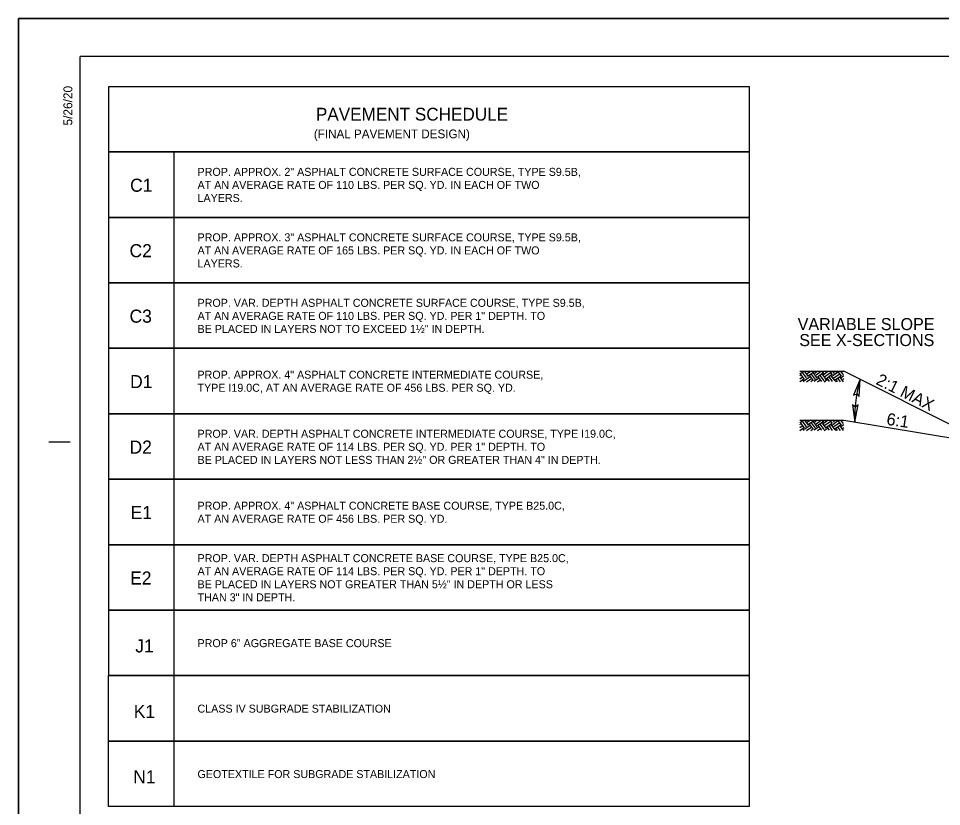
# Model space of a CAD drawing. Extents: x 1184121 to 1184397, y 1246506 to 1246661.
# Drawn here: x 1184121.1 to 1184197.8, y 1246595 to 1246660.5 of the extents above; entities that cross this region are included whole.
import ezdxf

# ---------------------------------------------------------------- set-up
doc = ezdxf.new("R2010")
doc.units = 0
for name, color, linetype in [('Sheet Data Field CELL', 7, 'Continuous'), ('Sheet Plan CELL', 7, 'Continuous'), ('Sheet Plot Border Outside CELL', 7, 'Continuous'), ('z - Construction', 7, 'Continuous')]:
    doc.layers.add(name, color=color, linetype=linetype)

msp = doc.modelspace()

# ---------------------------------------------------------------- linework, layer by layer
at = {"layer": 'Sheet Data Field CELL'}
for p, q in [((1184185.976, 1246631.202), (1184189.63, 1246631.202)), ((1184185.976, 1246631.202), (1184189.63, 1246631.202)), ((1184185.99, 1246630.99), (1184186.286, 1246631.202)), ((1184185.99, 1246630.99), (1184186.286, 1246631.202)), ((1184186.53, 1246630.645), (1184186.221, 1246631.075)), ((1184186.53, 1246630.645), (1184186.221, 1246631.075)), ((1184186.691, 1246630.761), (1184186.382, 1246631.19)), ((1184186.691, 1246630.761), (1184186.382, 1246631.19)), ((1184186.474, 1246631.175), (1184186.513, 1246631.203)), ((1184186.474, 1246631.175), (1184186.513, 1246631.203)), ((1184186.59, 1246631.014), (1184186.855, 1246631.204)), ((1184186.59, 1246631.014), (1184186.855, 1246631.204)), ((1184186.706, 1246630.853), (1184187.136, 1246631.162)), ((1184186.706, 1246630.853), (1184187.136, 1246631.162)), ((1184187.429, 1246630.64), (1184187.121, 1246631.069)), ((1184187.429, 1246630.64), (1184187.121, 1246631.069)), ((1184187.228, 1246631.147), (1184187.186, 1246631.205)), ((1184187.228, 1246631.147), (1184187.186, 1246631.205)), ((1184187.213, 1246631.054), (1184187.424, 1246631.206)), ((1184187.213, 1246631.054), (1184187.424, 1246631.206)), ((1184187.329, 1246630.893), (1184187.758, 1246631.202)), ((1184187.329, 1246630.893), (1184187.758, 1246631.202)), ((1184187.966, 1246631.026), (1184187.836, 1246631.207)), ((1184187.966, 1246631.026), (1184187.836, 1246631.207)), ((1184187.951, 1246630.933), (1184188.334, 1246631.208)), ((1184187.951, 1246630.933), (1184188.334, 1246631.208)), ((1184188.067, 1246630.772), (1184188.497, 1246631.081)), ((1184188.067, 1246630.772), (1184188.497, 1246631.081)), ((1184188.128, 1246631.141), (1184188.08, 1246631.208)), ((1184188.128, 1246631.141), (1184188.08, 1246631.208)), ((1184188.705, 1246630.905), (1184188.491, 1246631.202)), ((1184188.705, 1246630.905), (1184188.491, 1246631.202)), ((1184188.69, 1246630.813), (1184189.119, 1246631.121)), ((1184188.69, 1246630.813), (1184189.119, 1246631.121)), ((1184188.866, 1246631.021), (1184188.73, 1246631.209)), ((1184188.866, 1246631.021), (1184188.73, 1246631.209)), ((1184189.027, 1246631.136), (1184188.98, 1246631.202)), ((1184189.027, 1246631.136), (1184188.98, 1246631.202)), ((1184189.443, 1246630.784), (1184189.143, 1246631.202)), ((1184189.443, 1246630.784), (1184189.143, 1246631.202)), ((1184189.604, 1246630.9), (1184189.387, 1246631.202)), ((1184189.604, 1246630.9), (1184189.387, 1246631.202)), ((1184201.788, 1246625.123), (1184189.63, 1246631.202)), ((1184185.99, 1246630.827), (1184186.045, 1246630.866)), ((1184185.99, 1246630.827), (1184186.045, 1246630.866)), ((1184185.99, 1246630.583), (1184186.161, 1246630.705)), ((1184185.99, 1246630.583), (1184186.161, 1246630.705)), ((1184185.99, 1246630.338), (1184186.276, 1246630.544)), ((1184185.99, 1246630.338), (1184186.276, 1246630.544)), ((1184186.369, 1246630.529), (1184186.06, 1246630.959)), ((1184186.369, 1246630.529), (1184186.06, 1246630.959)), ((1184186.351, 1246630.327), (1184186.261, 1246630.452)), ((1184186.351, 1246630.327), (1184186.261, 1246630.452)), ((1184186.354, 1246630.437), (1184186.783, 1246630.746)), ((1184186.354, 1246630.437), (1184186.783, 1246630.746)), ((1184186.541, 1246630.327), (1184186.899, 1246630.584)), ((1184186.541, 1246630.327), (1184186.899, 1246630.584)), ((1184187.107, 1246630.408), (1184186.798, 1246630.838)), ((1184187.107, 1246630.408), (1184186.798, 1246630.838)), ((1184186.881, 1246630.327), (1184187.015, 1246630.423)), ((1184186.881, 1246630.327), (1184187.015, 1246630.423)), ((1184187.268, 1246630.524), (1184186.959, 1246630.954)), ((1184187.268, 1246630.524), (1184186.959, 1246630.954)), ((1184187.169, 1246630.371), (1184187.522, 1246630.625)), ((1184187.169, 1246630.371), (1184187.522, 1246630.625)), ((1184187.444, 1246630.732), (1184187.874, 1246631.041)), ((1184187.444, 1246630.732), (1184187.874, 1246631.041)), ((1184187.448, 1246630.327), (1184187.637, 1246630.464)), ((1184187.448, 1246630.327), (1184187.637, 1246630.464)), ((1184187.794, 1246630.359), (1184187.537, 1246630.717)), ((1184187.794, 1246630.359), (1184187.537, 1246630.717)), ((1184188.007, 1246630.403), (1184187.698, 1246630.833)), ((1184188.007, 1246630.403), (1184187.698, 1246630.833)), ((1184188.168, 1246630.519), (1184187.859, 1246630.949)), ((1184188.168, 1246630.519), (1184187.859, 1246630.949)), ((1184188.015, 1246630.327), (1184188.26, 1246630.504)), ((1184188.015, 1246630.327), (1184188.26, 1246630.504)), ((1184188.183, 1246630.611), (1184188.613, 1246630.92)), ((1184188.183, 1246630.611), (1184188.613, 1246630.92)), ((1184188.455, 1246630.345), (1184188.275, 1246630.596)), ((1184188.455, 1246630.345), (1184188.275, 1246630.596)), ((1184188.703, 1246630.34), (1184188.436, 1246630.712)), ((1184188.703, 1246630.34), (1184188.436, 1246630.712)), ((1184188.906, 1246630.398), (1184188.597, 1246630.828)), ((1184188.906, 1246630.398), (1184188.597, 1246630.828)), ((1184188.806, 1246630.651), (1184189.235, 1246630.96)), ((1184188.806, 1246630.651), (1184189.235, 1246630.96)), ((1184188.921, 1246630.49), (1184189.351, 1246630.799)), ((1184188.921, 1246630.49), (1184189.351, 1246630.799)), ((1184188.933, 1246630.336), (1184188.998, 1246630.383)), ((1184188.933, 1246630.336), (1184188.998, 1246630.383)), ((1184189.116, 1246630.332), (1184189.014, 1246630.475)), ((1184189.116, 1246630.332), (1184189.014, 1246630.475)), ((1184189.364, 1246630.327), (1184189.175, 1246630.591)), ((1184189.364, 1246630.327), (1184189.175, 1246630.591)), ((1184189.612, 1246630.322), (1184189.336, 1246630.707)), ((1184189.612, 1246630.322), (1184189.336, 1246630.707)), ((1184189.428, 1246630.692), (1184189.63, 1246630.837)), ((1184189.428, 1246630.692), (1184189.63, 1246630.837)), ((1184189.544, 1246630.53), (1184189.63, 1246630.593)), ((1184189.544, 1246630.53), (1184189.63, 1246630.593)), ((1184185.976, 1246627.149), (1184189.63, 1246627.149)), ((1184185.976, 1246627.149), (1184189.63, 1246627.149)), ((1184185.99, 1246626.938), (1184186.286, 1246627.15)), ((1184185.99, 1246626.938), (1184186.286, 1246627.15)), ((1184185.99, 1246626.775), (1184186.045, 1246626.814)), ((1184185.99, 1246626.775), (1184186.045, 1246626.814)), ((1184185.99, 1246626.53), (1184186.161, 1246626.653)), ((1184185.99, 1246626.53), (1184186.161, 1246626.653)), ((1184185.99, 1246626.286), (1184186.276, 1246626.492)), ((1184185.99, 1246626.286), (1184186.276, 1246626.492)), ((1184186.369, 1246626.477), (1184186.06, 1246626.906)), ((1184186.369, 1246626.477), (1184186.06, 1246626.906)), ((1184186.53, 1246626.592), (1184186.221, 1246627.022)), ((1184186.53, 1246626.592), (1184186.221, 1246627.022)), ((1184186.354, 1246626.384), (1184186.783, 1246626.693)), ((1184186.354, 1246626.384), (1184186.783, 1246626.693)), ((1184186.691, 1246626.708), (1184186.382, 1246627.138)), ((1184186.691, 1246626.708), (1184186.382, 1246627.138)), ((1184186.474, 1246627.123), (1184186.513, 1246627.151)), ((1184186.474, 1246627.123), (1184186.513, 1246627.151)), ((1184186.541, 1246626.275), (1184186.899, 1246626.532)), ((1184186.541, 1246626.275), (1184186.899, 1246626.532)), ((1184186.59, 1246626.962), (1184186.855, 1246627.152)), ((1184186.59, 1246626.962), (1184186.855, 1246627.152)), ((1184186.706, 1246626.8), (1184187.136, 1246627.109)), ((1184186.706, 1246626.8), (1184187.136, 1246627.109)), ((1184187.107, 1246626.356), (1184186.798, 1246626.785)), ((1184187.107, 1246626.356), (1184186.798, 1246626.785)), ((1184187.268, 1246626.471), (1184186.959, 1246626.901)), ((1184187.268, 1246626.471), (1184186.959, 1246626.901)), ((1184187.429, 1246626.587), (1184187.121, 1246627.017)), ((1184187.429, 1246626.587), (1184187.121, 1246627.017)), ((1184187.169, 1246626.319), (1184187.522, 1246626.572)), ((1184187.169, 1246626.319), (1184187.522, 1246626.572)), ((1184187.228, 1246627.094), (1184187.186, 1246627.153)), ((1184187.228, 1246627.094), (1184187.186, 1246627.153)), ((1184187.213, 1246627.002), (1184187.424, 1246627.153)), ((1184187.213, 1246627.002), (1184187.424, 1246627.153)), ((1184187.329, 1246626.841), (1184187.758, 1246627.149)), ((1184187.329, 1246626.841), (1184187.758, 1246627.149)), ((1184187.444, 1246626.68), (1184187.874, 1246626.988)), ((1184187.444, 1246626.68), (1184187.874, 1246626.988)), ((1184187.794, 1246626.306), (1184187.537, 1246626.664)), ((1184187.794, 1246626.306), (1184187.537, 1246626.664)), ((1184188.007, 1246626.351), (1184187.698, 1246626.78)), ((1184188.007, 1246626.351), (1184187.698, 1246626.78)), ((1184187.966, 1246626.973), (1184187.836, 1246627.154)), ((1184187.966, 1246626.973), (1184187.836, 1246627.154)), ((1184188.168, 1246626.466), (1184187.859, 1246626.896)), ((1184188.168, 1246626.466), (1184187.859, 1246626.896)), ((1184187.951, 1246626.881), (1184188.334, 1246627.156)), ((1184187.951, 1246626.881), (1184188.334, 1246627.156)), ((1184188.067, 1246626.72), (1184188.497, 1246627.029)), ((1184188.067, 1246626.72), (1184188.497, 1246627.029)), ((1184188.128, 1246627.089), (1184188.08, 1246627.155)), ((1184188.128, 1246627.089), (1184188.08, 1246627.155)), ((1184188.183, 1246626.559), (1184188.613, 1246626.867)), ((1184188.183, 1246626.559), (1184188.613, 1246626.867)), ((1184188.455, 1246626.293), (1184188.275, 1246626.544)), ((1184188.455, 1246626.293), (1184188.275, 1246626.544)), ((1184188.703, 1246626.288), (1184188.436, 1246626.659)), ((1184188.703, 1246626.288), (1184188.436, 1246626.659)), ((1184188.705, 1246626.852), (1184188.491, 1246627.149)), ((1184188.705, 1246626.852), (1184188.491, 1246627.149)), ((1184188.906, 1246626.345), (1184188.597, 1246626.775)), ((1184188.906, 1246626.345), (1184188.597, 1246626.775)), ((1184188.69, 1246626.76), (1184189.119, 1246627.069)), ((1184188.69, 1246626.76), (1184189.119, 1246627.069)), ((1184188.866, 1246626.968), (1184188.73, 1246627.157)), ((1184188.866, 1246626.968), (1184188.73, 1246627.157)), ((1184188.806, 1246626.599), (1184189.235, 1246626.908)), ((1184188.806, 1246626.599), (1184189.235, 1246626.908)), ((1184188.921, 1246626.438), (1184189.351, 1246626.747)), ((1184188.921, 1246626.438), (1184189.351, 1246626.747)), ((1184189.027, 1246627.084), (1184188.98, 1246627.149)), ((1184189.027, 1246627.084), (1184188.98, 1246627.149)), ((1184189.443, 1246626.731), (1184189.143, 1246627.149)), ((1184189.443, 1246626.731), (1184189.143, 1246627.149)), ((1184189.364, 1246626.275), (1184189.175, 1246626.538)), ((1184189.364, 1246626.275), (1184189.175, 1246626.538)), ((1184189.612, 1246626.27), (1184189.336, 1246626.654)), ((1184189.612, 1246626.27), (1184189.336, 1246626.654)), ((1184189.604, 1246626.847), (1184189.387, 1246627.149)), ((1184189.604, 1246626.847), (1184189.387, 1246627.149)), ((1184189.428, 1246626.639), (1184189.63, 1246626.784)), ((1184189.428, 1246626.639), (1184189.63, 1246626.784)), ((1184189.544, 1246626.478), (1184189.63, 1246626.54)), ((1184189.544, 1246626.478), (1184189.63, 1246626.54)), ((1184189.63, 1246627.149), (1184201.788, 1246625.123)), ((1184186.351, 1246626.275), (1184186.261, 1246626.399)), ((1184186.351, 1246626.275), (1184186.261, 1246626.399)), ((1184186.881, 1246626.275), (1184187.015, 1246626.371)), ((1184186.881, 1246626.275), (1184187.015, 1246626.371)), ((1184187.448, 1246626.275), (1184187.637, 1246626.411)), ((1184187.448, 1246626.275), (1184187.637, 1246626.411)), ((1184188.015, 1246626.275), (1184188.26, 1246626.451)), ((1184188.015, 1246626.275), (1184188.26, 1246626.451)), ((1184188.933, 1246626.283), (1184188.998, 1246626.33)), ((1184188.933, 1246626.283), (1184188.998, 1246626.33)), ((1184189.116, 1246626.28), (1184189.014, 1246626.423)), ((1184189.116, 1246626.28), (1184189.014, 1246626.423))]:
    msp.add_line(p, q, dxfattribs=at)
for points in [[(1184128.55, 1246654.882), (1184181.763, 1246654.882), (1184181.763, 1246649.44), (1184128.55, 1246649.44)], [(1184190.91, 1246629.113), (1184190.987, 1246630.538), (1184190.428, 1246629.215), (1184190.712, 1246629.334)], [(1184190.343, 1246628.407), (1184190.551, 1246626.996), (1184190.835, 1246628.403), (1184190.581, 1246628.23)]]:
    msp.add_lwpolyline(points, close=True, dxfattribs=at)
for points in [[(1184133.992, 1246643.997), (1184128.55, 1246643.997), (1184128.55, 1246649.44), (1184181.762, 1246649.44), (1184181.762, 1246643.997), (1184133.992, 1246643.997), (1184133.992, 1246649.44)], [(1184133.992, 1246638.554), (1184128.55, 1246638.554), (1184128.55, 1246643.997), (1184181.762, 1246643.997), (1184181.762, 1246638.554), (1184133.992, 1246638.554), (1184133.992, 1246643.997)], [(1184133.992, 1246633.112), (1184128.55, 1246633.112), (1184128.55, 1246638.554), (1184181.762, 1246638.554), (1184181.762, 1246633.112), (1184133.992, 1246633.112), (1184133.992, 1246638.554)], [(1184133.992, 1246627.669), (1184128.55, 1246627.669), (1184128.55, 1246633.112), (1184181.762, 1246633.112), (1184181.762, 1246627.669), (1184133.992, 1246627.669), (1184133.992, 1246633.112)], [(1184133.992, 1246622.227), (1184128.55, 1246622.227), (1184128.55, 1246627.669), (1184181.762, 1246627.669), (1184181.762, 1246622.227), (1184133.992, 1246622.227), (1184133.992, 1246627.669)], [(1184133.992, 1246616.785), (1184128.55, 1246616.785), (1184128.55, 1246622.227), (1184181.763, 1246622.227), (1184181.763, 1246616.785), (1184133.992, 1246616.785), (1184133.992, 1246622.227)], [(1184133.992, 1246611.343), (1184128.55, 1246611.343), (1184128.55, 1246616.785), (1184181.762, 1246616.785), (1184181.762, 1246611.343), (1184133.992, 1246611.343), (1184133.992, 1246616.785)], [(1184133.99, 1246605.901), (1184128.548, 1246605.901), (1184128.548, 1246611.343), (1184181.761, 1246611.343), (1184181.761, 1246605.901), (1184133.99, 1246605.901), (1184133.99, 1246611.343)], [(1184133.987, 1246600.459), (1184128.545, 1246600.459), (1184128.545, 1246605.901), (1184181.759, 1246605.901), (1184181.759, 1246600.459), (1184133.987, 1246600.459), (1184133.987, 1246605.901)], [(1184133.987, 1246595.017), (1184128.545, 1246595.017), (1184128.545, 1246600.459), (1184181.759, 1246600.459), (1184181.759, 1246595.017), (1184133.987, 1246595.017), (1184133.987, 1246600.459)]]:
    msp.add_lwpolyline(points, dxfattribs=at)
msp.add_arc((1184202.643, 1246627.305), 12.096, 164.50116, 181.46653, dxfattribs=at)
at = {"layer": 'Sheet Plan CELL'}
for p, q in [((1184126.181, 1246508.875), (1184126.184, 1246657.364)), ((1184358.423, 1246657.364), (1184126.184, 1246657.364)), ((1184123.582, 1246625.344), (1184125.343, 1246625.347))]:
    msp.add_line(p, q, dxfattribs=at)
at = {"layer": 'Sheet Plot Border Outside CELL'}
msp.add_lwpolyline([(1184121.05, 1246660.53), (1184360.324, 1246660.53), (1184360.324, 1246505.708), (1184121.05, 1246505.708)], close=True, dxfattribs=at)
at = {"layer": 'z - Construction'}
for p, q in [((1184360.324, 1246660.53), (1184121.05, 1246660.53)), ((1184121.05, 1246660.53), (1184121.05, 1246505.708))]:
    msp.add_line(p, q, dxfattribs=at)

# ---------------------------------------------------------------- texts
at = {"layer": 'Sheet Data Field CELL'}
for s, height, p in [('PAVEMENT SCHEDULE', 1.06425, (1184145.765, 1246652.039)), ('(FINAL PAVEMENT DESIGN)', 0.72391, (1184145.598, 1246650.573)), ('PROP. APPROX. 2" ASPHALT CONCRETE SURFACE COURSE, TYPE S9.5B, ', 0.66516, (1184135.932, 1246647.445)), ('C1', 1.0864, (1184130.327, 1246646.125)), ('AT AN AVERAGE RATE OF 110 LBS. PER SQ. YD. IN EACH OF TWO', 0.66516, (1184135.932, 1246646.359)), ('LAYERS.', 0.6652, (1184135.932, 1246645.274)), ('PROP. APPROX. 3" ASPHALT CONCRETE SURFACE COURSE, TYPE S9.5B, ', 0.66516, (1184135.932, 1246642.001)), ('C2', 1.0864, (1184130.281, 1246640.682)), ('AT AN AVERAGE RATE OF 165 LBS. PER SQ. YD. IN EACH OF TWO ', 0.66516, (1184135.932, 1246640.916)), ('LAYERS.', 0.6652, (1184135.932, 1246639.831)), ('PROP. VAR. DEPTH ASPHALT CONCRETE SURFACE COURSE, TYPE S9.5B,', 0.66516, (1184135.932, 1246636.558)), ('C3', 1.0864, (1184130.282, 1246635.24)), ('AT AN AVERAGE RATE OF 110 LBS. PER SQ. YD. PER 1" DEPTH. TO', 0.66516, (1184135.932, 1246635.473)), ('BE PLACED IN LAYERS NOT TO EXCEED 1½" IN DEPTH.', 0.66516, (1184135.932, 1246634.388)), ('PROP. APPROX. 4" ASPHALT CONCRETE INTERMEDIATE COURSE,', 0.66516, (1184135.926, 1246630.584)), ('D1', 1.0864, (1184130.327, 1246629.798)), ('TYPE I19.0C, AT AN AVERAGE RATE OF 456 LBS. PER SQ. YD.', 0.66516, (1184135.926, 1246629.499)), ('PROP. VAR. DEPTH ASPHALT CONCRETE INTERMEDIATE COURSE, TYPE I19.0C,', 0.66516, (1184135.932, 1246625.674)), ('D2', 1.0864, (1184130.281, 1246624.356)), ('AT AN AVERAGE RATE OF 114 LBS. PER SQ. YD. PER 1" DEPTH. TO', 0.66516, (1184135.932, 1246624.589)), ('BE PLACED IN LAYERS NOT LESS THAN 2½" OR GREATER THAN 4" IN DEPTH.', 0.66516, (1184135.932, 1246623.503)), ('PROP. APPROX. 4" ASPHALT CONCRETE BASE COURSE, TYPE B25.0C,', 0.66517, (1184135.932, 1246619.693)), ('E1', 1.0864, (1184130.368, 1246618.913)), ('AT AN AVERAGE RATE OF 456 LBS. PER SQ. YD.', 0.66517, (1184135.932, 1246618.608)), ('PROP. VAR. DEPTH ASPHALT CONCRETE BASE COURSE, TYPE B25.0C,', 0.66516, (1184135.932, 1246615.333)), ('E2', 1.0864, (1184130.328, 1246613.471)), ('AT AN AVERAGE RATE OF 114 LBS. PER SQ. YD. PER 1" DEPTH. TO', 0.66516, (1184135.932, 1246614.248)), ('BE PLACED IN LAYERS NOT GREATER THAN 5½" IN DEPTH OR LESS', 0.66516, (1184135.932, 1246613.162)), ('THAN 3" IN DEPTH.', 0.66516, (1184135.932, 1246612.077)), ('J1', 1.0864, (1184130.758, 1246607.824)), ('PROP 6" AGGREGATE BASE COURSE', 0.66516, (1184135.93, 1246608.267)), ('K1', 1.0864, (1184130.631, 1246602.382)), ('CLASS IV SUBGRADE STABILIZATION', 0.66516, (1184135.927, 1246602.825)), ('N1', 1.0864, (1184130.59, 1246596.94)), ('GEOTEXTILE FOR SUBGRADE STABILIZATION', 0.66516, (1184135.927, 1246597.383))]:
    msp.add_text(s, height=height, dxfattribs=at).set_placement(p)
for s, rotation, p in [('VARIABLE SLOPE', 360, (1184185.8, 1246634.624)), ('SEE X-SECTIONS', 360, (1184185.933, 1246633.294)), ('2:1 MAX', 333.43475, (1184192.231, 1246630.163)), ('6:1', 351.39374, (1184193.134, 1246626.763))]:
    msp.add_text(s, height=1, rotation=rotation, dxfattribs=at).set_placement(p)
at = {"layer": 'Sheet Plan CELL'}
msp.add_text('5/26/20', height=0.7389, rotation=90, dxfattribs=at).set_placement((1184125.526, 1246651.63))

doc.saveas('drawing.dxf')
